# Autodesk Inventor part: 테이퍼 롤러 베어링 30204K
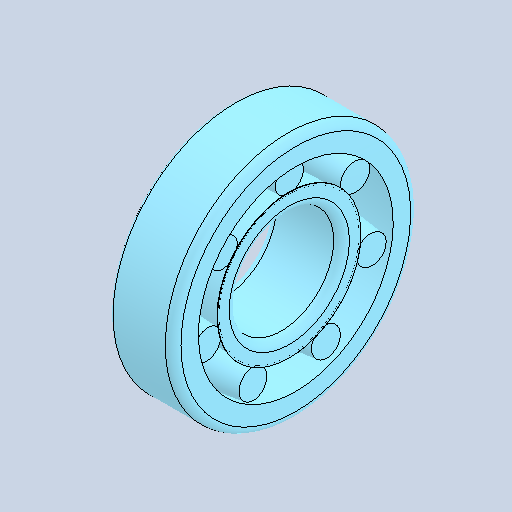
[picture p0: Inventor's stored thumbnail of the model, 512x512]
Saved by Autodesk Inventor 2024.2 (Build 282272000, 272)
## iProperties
Created: 2026-01
Part Number: 테이퍼 롤러 베어링 30204K
Material: 강철, 연강
Description: 테이퍼 롤러 베어링
Document SubType Name: Modeling
Designer: home
Density: 7.85 g/cm^3
Appearance: 기본값
Author: jhkim
Sending System: Autodesk Inventor 2026
Preprocessor: ST-DEVELOPER v20.1
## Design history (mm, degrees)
feature "Solid1"
feature "Solid1:1"
node "솔리드1"
node "솔리드2"
